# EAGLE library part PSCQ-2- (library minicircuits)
Power Splitter / Combiner 2 Way-90° Source: minicircuits.com .. PSCQ-2-10.5.pdf
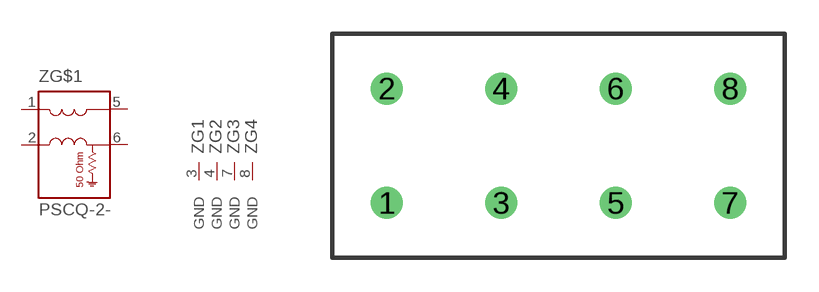
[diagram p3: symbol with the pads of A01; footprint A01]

Designator prefix Z; gates G1=GROUND G2=GROUND G3=GROUND G$1=POWER-SPLITTER-EXTERNAL_50OHM G4=GROUND

## PSCQ-2-10.5 (OC_FARNELL: unknown; OC_NEWARK: unknown), PSCQ-2-120 (OC_FARNELL: unknown; OC_NEWARK: unknown)  [A01]
1  G$1:SUM  in
2  G$1:PORT1  in
3  G1:GND  pwr
4  G2:GND  pwr
5  G$1:PORT2  in
6  G$1:X  in
7  G3:GND  pwr
8  G4:GND  pwr

## Footprint A01 (pad centres in mm)
CASE STYLE A01 Source: minicircuits.com .. PBP-10.7+.pdf
drill 0.9 pad 1.422 round: 1 -7.62,-2.54; 2 -7.62,2.54; 3 -2.54,-2.54; 4 -2.54,2.54; 5 2.54,-2.54; 6 2.54,2.54; 7 7.62,-2.54; 8 7.62,2.54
